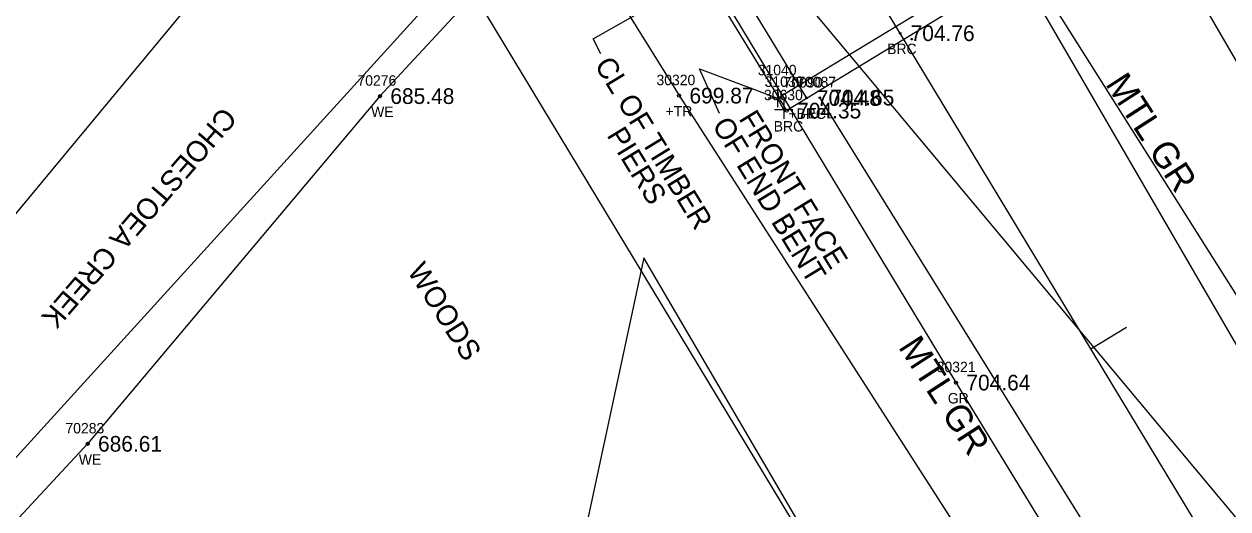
# Model space of a CAD drawing. Extents: x 1375131 to 1378678, y 999028 to 1004053.
# Drawn here: x 1377295.1 to 1377410.5, y 1001592.8 to 1001639.2 of the extents above; entities that cross this region are included whole.
import ezdxf

# ---------------------------------------------------------------- set-up
doc = ezdxf.new("R2010")
doc.units = 0
for name, color, linetype in [('Default', 7, 'Continuous'), ('RD_EX_Bridge', 7, 'Continuous'), ('RD_EX_Bridge_txCode', 7, 'Continuous'), ('RD_EX_DV_Prop', 7, 'Continuous'), ('RD_EX_GuardRail', 7, 'Continuous'), ('RD_EX_GuardRail_txCode', 7, 'Continuous'), ('RD_EX_H2O', 7, 'Continuous'), ('RD_EX_H2O_txCode', 7, 'Continuous'), ('RD_EX_Road', 7, 'Continuous'), ('RD_EX_Road_txCode', 7, 'Continuous'), ('RD_EX_RW', 7, 'Continuous'), ('RD_EX_SU_Elec', 7, 'Continuous'), ('RD_EX_TX_Bridge_ELEV', 7, 'Continuous'), ('RD_EX_TX_GuardRail_ELEV', 7, 'Continuous'), ('RD_EX_TX_H2O_ELEV', 7, 'Continuous'), ('RD_EX_TX_Road_ELEV', 7, 'Continuous'), ('RD_EX_TX_VEG_ELEV', 7, 'Continuous'), ('RD_EX_VEG', 7, 'Continuous'), ('RD_EX_VEG_txCode', 7, 'Continuous'), ('RD_HC_Cl', 7, 'Continuous'), ('RD_HC_Data_Tic', 7, 'Continuous'), ('RD_SMD_Locator', 7, 'Continuous'), ('RD_TX_Misc1', 7, 'Continuous'), ('RD_TX_Misc2', 7, 'Continuous')]:
    doc.layers.add(name, color=color, linetype=linetype)

msp = doc.modelspace()

# ---------------------------------------------------------------- linework, layer by layer
at = {"layer": 'Default'}
for p, q in [((1377368.16, 1001632.13), (1377366.41, 1001632.13)), ((1377367.29, 1001633.01), (1377367.29, 1001631.26)), ((1377368.78, 1001631.02), (1377367.03, 1001631.02)), ((1377367.9, 1001631.9), (1377367.9, 1001630.15))]:
    msp.add_line(p, q, dxfattribs=at)
at = {"layer": 'RD_EX_Bridge'}
for points in [[(1377391.5, 1001645.13), (1377368.19, 1001630.94), (1377329, 1001694.93), (1377352.49, 1001709.16), (1377391.54, 1001645.17)], [(1377331.33, 1001695.91), (1377370.08, 1001632.15)], [(1377367.9, 1001631.02), (1377367.29, 1001632.13), (1377390.82, 1001646.41)]]:
    msp.add_lwpolyline(points, dxfattribs=at)
at = {"layer": 'RD_EX_DV_Prop'}
msp.add_lwpolyline([(1377336.79, 1001644.47), (1377261.88, 1001561.95), (1377219.07, 1001552.06), (1377161.86, 1001551.74), (1377137.12, 1001561.19), (1377067.04, 1001536.73), (1376960.14, 1001529.08), (1376841.39, 1001566.65), (1376720.96, 1001615.31), (1376646.89, 1001572.2), (1376582.24, 1001597.38), (1376530.03, 1001524.91), (1376479.01, 1001492.21), (1376423.76, 1001471.27), (1376406.38, 1001416.23), (1376319.08, 1001330.17), (1376238.95, 1001217.2), (1376238.09, 1001132.92), (1376171.56, 1000915.51), (1376168.19, 1000884.88), (1376152.25, 1000873.16), (1376095.21, 1000886.38)], dxfattribs=at)
at = {"layer": 'RD_EX_GuardRail'}
for points in [[(1377413.07, 1001610.45), (1377381.61, 1001660.28), (1377356.8, 1001700.83), (1377329.73, 1001745.67), (1377300.76, 1001793.63), (1377267.9, 1001848.65)], [(1377243.23, 1001836.32), (1377270.94, 1001792.3), (1377296.9, 1001749.47), (1377330.01, 1001694.45), (1377359.06, 1001646.8), (1377384.4, 1001604.87), (1377407.06, 1001567.74), (1377414.21, 1001555.7)]]:
    msp.add_lwpolyline(points, dxfattribs=at)
at = {"layer": 'RD_EX_H2O'}
for points in [[(1377334.46, 1001660.58), (1377318.22, 1001649.94), (1377286.5, 1001611.68), (1377286.5, 1001611.68), (1377237.87, 1001575.18), (1377169.71, 1001581.47), (1377110, 1001563.58), (1377053.34, 1001538.73), (1377032.88, 1001532.42), (1376974.36, 1001543.19), (1376926.22, 1001584.14)], [(1377346.87, 1001651.39), (1377329.21, 1001632.33), (1377301.2, 1001599), (1377255.16, 1001549.42), (1377172.11, 1001555.1), (1377120.45, 1001543.09), (1377120.45, 1001543.09), (1377055.21, 1001526.73), (1377035.21, 1001521.3), (1376967.62, 1001528.25), (1376929.58, 1001558)]]:
    msp.add_lwpolyline(points, dxfattribs=at)
at = {"layer": 'RD_EX_Road'}
for points in [[(1377899.67, 1000800.29), (1377898.72, 1000801.84), (1377870.31, 1000849.94), (1377847.28, 1000887.89), (1377815.15, 1000940.58), (1377781.51, 1000995.26), (1377748.62, 1001049.21), (1377716.58, 1001099.53), (1377686.67, 1001148.78), (1377656.47, 1001199.11), (1377629.54, 1001244.18), (1377599.89, 1001292.67), (1377570.87, 1001341.43), (1377539.83, 1001392.47), (1377511.01, 1001440.31), (1377480.72, 1001490), (1377449.73, 1001541.49), (1377420.9, 1001591.95), (1377390.45, 1001644.41)], [(1377883.75, 1000788.5), (1377882.63, 1000790.22), (1377852.26, 1000839.6), (1377828.46, 1000879.31), (1377797, 1000930.66), (1377763.07, 1000986.65), (1377731.87, 1001037.81), (1377700.31, 1001089.98), (1377670.43, 1001138.24), (1377639.73, 1001190.03), (1377611.89, 1001234.23), (1377582.78, 1001282.57), (1377552.22, 1001331.03), (1377522.24, 1001382.35), (1377494.26, 1001430.19), (1377463.17, 1001481.14), (1377433.42, 1001531.29), (1377403.14, 1001580.98), (1377371.36, 1001632.19)]]:
    msp.add_lwpolyline(points, dxfattribs=at)
at = {"layer": 'RD_EX_RW'}
msp.add_line((1376979.85, 1002235.45), (1377524.04, 1001334.45), dxfattribs=at)
at = {"layer": 'RD_EX_SU_Elec'}
msp.add_lwpolyline([(1377317.71, 1001704), (1377525.76, 1001454.69), (1377725.47, 1001622.6)], dxfattribs=at)
at = {"layer": 'RD_EX_VEG'}
for points in [[(1376925.29, 1002323.56), (1376964.39, 1002271.55), (1376999.6, 1002220.98), (1377033.75, 1002161.52), (1377072.45, 1002098.21), (1377110.65, 1002037.08), (1377148.79, 1001977.33), (1377186.7, 1001917.17), (1377238.51, 1001843.58), (1377265.98, 1001789.91), (1377290.89, 1001746.87), (1377322.19, 1001689.75), (1377357.87, 1001632.38)], [(1377321.3, 1001854.67), (1377275.03, 1001863.5), (1377273.88, 1001860.91), (1377305.16, 1001803.79), (1377331.05, 1001757.48), (1377351.19, 1001714.88), (1377403.26, 1001649.45), (1377431.16, 1001601.42)], [(1377357.87, 1001632.38), (1377400.8, 1001565.51), (1377430.45, 1001516.67), (1377459.64, 1001469), (1377495.02, 1001411.92)], [(1377354.5, 1001616.83), (1377345.52, 1001575.01), (1377297, 1001559.15)], [(1377432.68, 1001366.18), (1377470.24, 1001403.17), (1377475.5, 1001410), (1377354.5, 1001616.83)]]:
    msp.add_lwpolyline(points, dxfattribs=at)
at = {"layer": 'RD_HC_Cl'}
msp.add_line((1377008.1, 1002252.51), (1377552.29, 1001351.51), dxfattribs=at)
at = {"layer": 'RD_HC_Data_Tic'}
msp.add_line((1377397.31, 1001608.11), (1377400.73, 1001610.17), dxfattribs=at)
at = {"layer": 'RD_SMD_Locator'}
for centre, radius in [((1377379.06, 1001638.36), 0.075), ((1377380.15, 1001637.79), 0.075), ((1377329.21, 1001632.33), 0.15), ((1377357.87, 1001632.38), 0.15), ((1377370.08, 1001632.15), 0.075), ((1377371.36, 1001632.19), 0.075), ((1377368.19, 1001630.94), 0.15), ((1377384.4, 1001604.87), 0.15), ((1377301.2, 1001599), 0.15)]:
    msp.add_circle(centre, radius, dxfattribs=at)
at = {"layer": 'RD_TX_Misc1'}
for points in [[(1377350.39, 1001636.4), (1377349.63, 1001637.81), (1377362.24, 1001644.97)], [(1377361.76, 1001630.66), (1377359.83, 1001634.96), (1377367.29, 1001632.13)]]:
    msp.add_lwpolyline(points, dxfattribs=at)

# ---------------------------------------------------------------- texts
at = {"layer": 'Default'}
for s, p in [('31040', (1377365.41, 1001634.33)), ('31039', (1377366.07, 1001633.22))]:
    msp.add_text(s, height=1, dxfattribs=at).set_placement(p)
at = {"layer": 'RD_EX_Bridge_txCode'}
for s, p in [('BRC', (1377377.81, 1001636.36)), ('70090', (1377367.89, 1001633.15)), ('30630', (1377366.01, 1001631.94)), ('+BRC', (1377368.34, 1001630.15)), ('BRC', (1377366.94, 1001628.94))]:
    msp.add_text(s, height=1, dxfattribs=at).set_placement(p)
at = {"layer": 'RD_EX_GuardRail_txCode'}
for s, p in [('30321', (1377382.56, 1001605.87)), ('GR', (1377383.62, 1001602.87))]:
    msp.add_text(s, height=1, dxfattribs=at).set_placement(p)
at = {"layer": 'RD_EX_H2O_txCode'}
for s, p in [('70276', (1377327.06, 1001633.33)), ('WE', (1377328.37, 1001630.33)), ('70283', (1377299.08, 1001600)), ('WE', (1377300.36, 1001597))]:
    msp.add_text(s, height=1, dxfattribs=at).set_placement(p)
at = {"layer": 'RD_EX_Road_txCode'}
for s, p in [('70087', (1377369.2, 1001633.19)), ('-EPL', (1377369.75, 1001630.19))]:
    msp.add_text(s, height=1, dxfattribs=at).set_placement(p)
at = {"layer": 'RD_EX_TX_Bridge_ELEV'}
for s, p in [('704.76', (1377380.06, 1001637.61)), ('704.48', (1377371.08, 1001631.4)), ('704.35', (1377369.19, 1001630.19))]:
    msp.add_text(s, height=1.5, dxfattribs=at).set_placement(p)
at = {"layer": 'RD_EX_TX_GuardRail_ELEV'}
msp.add_text('704.64', height=1.5, dxfattribs=at).set_placement((1377385.4, 1001604.12))
at = {"layer": 'RD_EX_TX_H2O_ELEV'}
for s, p in [('685.48', (1377330.21, 1001631.58)), ('686.61', (1377302.2, 1001598.25))]:
    msp.add_text(s, height=1.5, dxfattribs=at).set_placement(p)
at = {"layer": 'RD_EX_TX_Road_ELEV'}
msp.add_text('704.65', height=1.5, dxfattribs=at).set_placement((1377372.36, 1001631.44))
at = {"layer": 'RD_EX_TX_VEG_ELEV'}
msp.add_text('699.87', height=1.5, dxfattribs=at).set_placement((1377358.87, 1001631.63))
at = {"layer": 'RD_EX_VEG_txCode'}
for s, p in [('30320', (1377355.71, 1001633.38)), ('+TR', (1377356.58, 1001630.38))]:
    msp.add_text(s, height=1, dxfattribs=at).set_placement(p)
at = {"layer": 'RD_TX_Misc1'}
for s, height, rotation, p in [('CL OF TIMBER', 2, 301.4075, (1377349.72, 1001635.32)), ('MTL GR', 2.5, 302.8608, (1377398.66, 1001633.49)), ('FRONT FACE', 2, 301.4075, (1377363.54, 1001630.18)), ('OF END BENT', 2, 301.4075, (1377360.99, 1001629.55)), (' PIERS', 2, 301.4075, (1377350.51, 1001629.22)), ('MTL GR', 2.5, 302.8608, (1377378.83, 1001608.28))]:
    msp.add_text(s, height=height, rotation=rotation, dxfattribs=at).set_placement(p)
at = {"layer": 'RD_TX_Misc2'}
for s, rotation, p in [('CHOESTOEA CREEK', 229.2113, (1377314.14, 1001631.42)), ('WOODS', 302.3586, (1377331.78, 1001615.55))]:
    msp.add_text(s, height=2, rotation=rotation, dxfattribs=at).set_placement(p)

doc.saveas('drawing.dxf')
